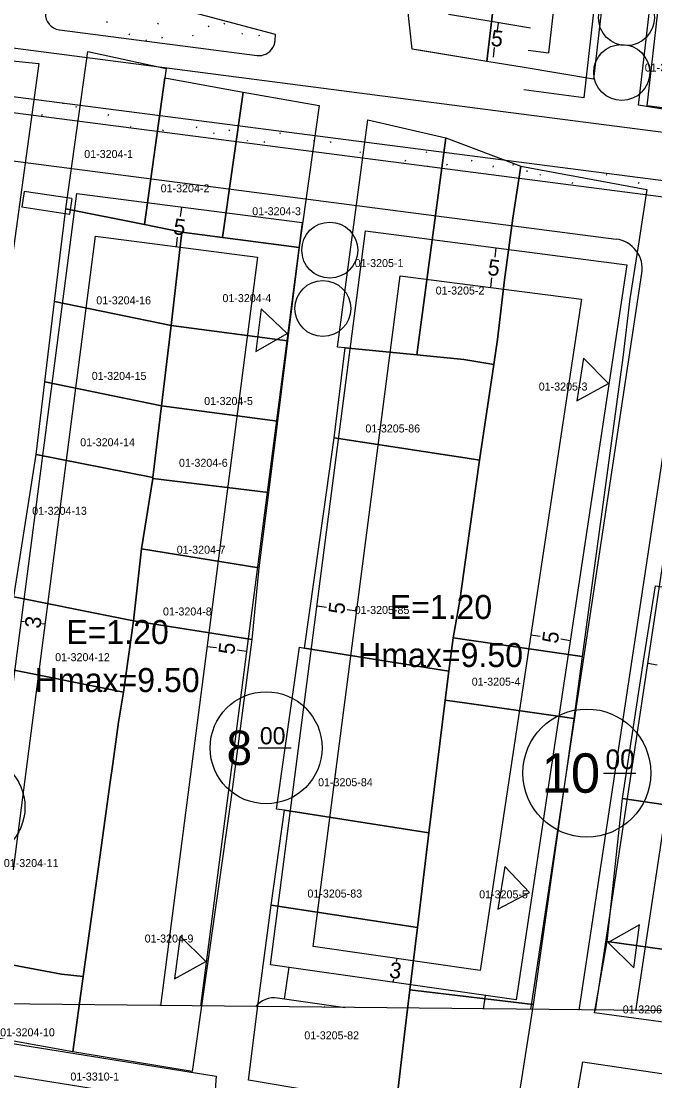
# Model space of a CAD drawing. Extents: x 419396 to 421519, y 4453567 to 4456767.
# Drawn here: x 420470.7 to 420549.9, y 4454304 to 4454436.5 of the extents above; entities that cross this region are included whole.
import ezdxf

# ---------------------------------------------------------------- set-up
doc = ezdxf.new("R2010")
doc.units = 0
for name, color, linetype in [('0_KADASTRO', 7, 'Continuous'), ('Level 16', 7, 'Continuous'), ('Level 20', 7, 'Continuous'), ('Level 28', 7, 'Continuous'), ('Level 29', 7, 'Continuous'), ('Level 30', 7, 'Continuous'), ('Level 41', 7, 'Continuous'), ('Level 53', 7, 'Continuous'), ('Level 55', 7, 'Continuous'), ('Level 58', 7, 'Continuous'), ('Level 62', 7, 'Continuous'), ('Y_Lejant', 7, 'Continuous')]:
    doc.layers.add(name, color=color, linetype=linetype)

msp = doc.modelspace()

# ---------------------------------------------------------------- linework, layer by layer
at = {"layer": '0_KADASTRO'}
for points in [[(420517.81, 4454449.01), (420521.76, 4454448.38), (420530.73, 4454446.96), (420528.91, 4454431.42), (420520.67, 4454432.78), (420519.55, 4454432.97)], [(420528.91, 4454431.42), (420530.73, 4454446.96), (420531.74, 4454446.8), (420544.03, 4454444.85), (420542.26, 4454429.23), (420533.58, 4454430.66)], [(420547.89, 4454425.95), (420548.01, 4454426.99), (420549.96, 4454443.91), (420562.54, 4454441.84), (420560.5, 4454423.87)], [(420476.26, 4454413.01), (420479.02, 4454432.68), (420488.79, 4454430.55), (420488.63, 4454429.4), (420486.07, 4454411.03)], [(420463.19, 4454405.98), (420463.73, 4454432.07), (420472.89, 4454431.17), (420469.31, 4454405.36)], [(420486.07, 4454411.03), (420488.63, 4454429.4), (420498.45, 4454427.58), (420495.85, 4454409.42), (420490.77, 4454410.08)], [(420495.85, 4454409.42), (420498.45, 4454427.58), (420507.93, 4454425.92), (420505.44, 4454408.19)], [(420510.21, 4454395.72), (420514.01, 4454424.15), (420523.76, 4454421.89), (420520.14, 4454394.75), (420511.17, 4454395.62)], [(420520.14, 4454394.75), (420523.76, 4454421.89), (420533.17, 4454418.32), (420532.14, 4454411.84), (420531.11, 4454404.12), (420530.25, 4454396.67), (420529.78, 4454393.54), (420526.05, 4454394.18)], [(420524.69, 4454359.39), (420525.54, 4454364.05), (420526.73, 4454372.71), (420527.97, 4454381.62), (420529.78, 4454393.54), (420530.25, 4454396.67), (420531.11, 4454404.12), (420532.14, 4454411.84), (420533.17, 4454418.32), (420548.92, 4454415.41), (420547.91, 4454408.9), (420546.8, 4454401.78), (420545.92, 4454394.45), (420540.84, 4454357.06)], [(420474.82, 4454401.44), (420476.26, 4454413.01), (420486.07, 4454411.03), (420490.77, 4454410.08), (420489.42, 4454398.42)], [(420489.42, 4454398.42), (420490.77, 4454410.08), (420495.85, 4454409.42), (420505.44, 4454408.19), (420503.99, 4454396.5)], [(420473.61, 4454391.38), (420474.82, 4454401.44), (420489.42, 4454398.42), (420488.22, 4454388.39)], [(420488.22, 4454388.39), (420489.42, 4454398.42), (420503.99, 4454396.5), (420502.74, 4454386.48)], [(420509.81, 4454384.38), (420511.17, 4454395.62), (420520.14, 4454394.75), (420526.05, 4454394.18), (420529.78, 4454393.54), (420527.97, 4454381.62), (420526.19, 4454381.89), (420524.51, 4454382.14)], [(420472.53, 4454382.3), (420473.61, 4454391.38), (420488.22, 4454388.39), (420487.15, 4454379.44), (420483.97, 4454380.07)], [(420487.13, 4454379.3), (420487.15, 4454379.44), (420488.22, 4454388.39), (420502.74, 4454386.48), (420501.6, 4454377.55)], [(420506.1, 4454358.12), (420508.55, 4454375.47), (420509.81, 4454384.38), (420524.51, 4454382.14), (420526.19, 4454381.89), (420527.97, 4454381.62), (420526.73, 4454372.71), (420525.54, 4454364.05), (420524.69, 4454359.39), (420524.16, 4454355.23), (420523.36, 4454355.36)], [(420469.75, 4454364.53), (420472.53, 4454382.3), (420483.97, 4454380.07), (420487.15, 4454379.44), (420487.13, 4454379.3), (420485.73, 4454370.5), (420484.71, 4454361.53), (420482.21, 4454362.03)], [(420485.73, 4454370.5), (420487.13, 4454379.3), (420501.6, 4454377.55), (420500.39, 4454368.16)], [(420484.71, 4454361.53), (420485.73, 4454370.5), (420500.39, 4454368.16), (420499.53, 4454359.17)], [(420545.88, 4454339.32), (420548.57, 4454357.03), (420549.99, 4454365.88), (420564.3, 4454363.71), (420579.28, 4454361.42), (420575.3, 4454334.97)], [(420468.56, 4454355.59), (420469.75, 4454364.53), (420482.21, 4454362.03), (420484.71, 4454361.53), (420483.46, 4454352.62), (420481.02, 4454353.11), (420469.35, 4454355.44)], [(420477.11, 4454307.65), (420478.42, 4454317.06), (420480.49, 4454331.99), (420481.79, 4454341.35), (420482.11, 4454343.64), (420482.84, 4454348.86), (420483.46, 4454352.62), (420484.71, 4454361.53), (420499.53, 4454359.17), (420496.85, 4454338.86), (420492.03, 4454305.19)], [(420523.71, 4454351.6), (420524.16, 4454355.23), (420524.69, 4454359.39), (420540.84, 4454357.06), (420539.78, 4454349.33), (420538.68, 4454349.49), (420526.41, 4454351.22)], [(420502.61, 4454338), (420505.49, 4454358.21), (420506.1, 4454358.12), (420523.36, 4454355.36), (420524.16, 4454355.23), (420523.71, 4454351.6), (420521.65, 4454335.01), (420503.6, 4454337.85)], [(420464.15, 4454319.52), (420465.35, 4454328.46), (420468.56, 4454355.59), (420469.35, 4454355.44), (420481.02, 4454353.11), (420483.46, 4454352.62), (420482.84, 4454348.86), (420482.11, 4454343.64), (420481.79, 4454341.35), (420480.49, 4454331.99), (420478.42, 4454317.06), (420475.72, 4454317.38), (420464.78, 4454319.41)], [(420519.29, 4454315.41), (420520.23, 4454323.21), (420521.65, 4454335.01), (420523.71, 4454351.6), (420526.41, 4454351.22), (420538.68, 4454349.49), (420539.78, 4454349.33), (420534.7, 4454313.56)], [(420543.95, 4454321.44), (420545.88, 4454339.32), (420575.3, 4454334.97), (420573.98, 4454326.07), (420560.65, 4454327.96), (420559.3, 4454319.29), (420558.31, 4454319.44)], [(420501.92, 4454325.99), (420503.6, 4454337.85), (420521.65, 4454335.01), (420520.23, 4454323.21)], [(420499.08, 4454304.11), (420500.26, 4454313.42), (420501.92, 4454325.99), (420520.23, 4454323.21), (420519.29, 4454315.41), (420518.71, 4454310.59), (420517.55, 4454300.99)], [(420542.37, 4454312.53), (420543.95, 4454321.44), (420558.31, 4454319.44), (420556.51, 4454310.61)], [(420463.48, 4454310.11), (420464.78, 4454319.41), (420475.72, 4454317.38), (420478.42, 4454317.06), (420477.11, 4454307.65)], [(420517.03, 4454297.83), (420517.4, 4454300.09), (420517.4, 4454300.1), (420517.55, 4454300.99), (420518.71, 4454310.59), (420519.29, 4454315.41), (420534.7, 4454313.56), (420531.93, 4454295.77), (420519.85, 4454297.44)], [(420465.63, 4454305.27), (420466.42, 4454309.19), (420495.07, 4454304.61), (420494.76, 4454300.61)], [(420539.38, 4454297.51), (420540.9, 4454306.39), (420569.61, 4454302.15), (420568.22, 4454293.26), (420562.81, 4454294.18), (420555.36, 4454295.46), (420554.37, 4454295.62), (420553.37, 4454295.8), (420541.97, 4454297.2)]]:
    msp.add_lwpolyline(points, close=True, dxfattribs=at)
at = {"layer": 'Level 16'}
for p, q in [((420500.69, 4454400.53), (420500.03, 4454395.17)), ((420503.93, 4454397.41), (420500.69, 4454400.53)), ((420500.03, 4454395.17), (420503.93, 4454397.41)), ((420540.98, 4454394.36), (420540.18, 4454389.02)), ((420544.14, 4454391.16), (420540.98, 4454394.36)), ((420540.18, 4454389.02), (420544.14, 4454391.16)), ((420531.14, 4454330.83), (420530.28, 4454325.5)), ((420534.26, 4454327.59), (420531.14, 4454330.83)), ((420530.28, 4454325.5), (420534.26, 4454327.59)), ((420548.02, 4454323.52), (420544.09, 4454321.34)), ((420547.29, 4454318.17), (420548.02, 4454323.52)), ((420490.56, 4454322.12), (420489.82, 4454316.77)), ((420493.76, 4454318.95), (420490.56, 4454322.12)), ((420544.09, 4454321.34), (420547.29, 4454318.17)), ((420489.82, 4454316.77), (420493.76, 4454318.95))]:
    msp.add_line(p, q, dxfattribs=at)
at = {"layer": 'Level 20'}
for p, q in [((420544.46, 4454501.85), (420536.64, 4454432.5)), ((420530.32, 4454436.22), (420530.17, 4454435.03)), ((420529.73, 4454431.98), (420529.88, 4454433.17)), ((420534.06, 4454432.84), (420536.64, 4454432.5)), ((420490.72, 4454413.23), (420490.57, 4454412.04)), ((420467.77, 4454315.93), (420479.94, 4454409.59)), ((420479.94, 4454409.59), (420500.22, 4454406.96)), ((420490.08, 4454408.28), (420490.23, 4454409.47)), ((420530.04, 4454408.15), (420529.89, 4454406.96)), ((420500.22, 4454406.96), (420488.07, 4454313.42)), ((420507.18, 4454320.82), (420518.07, 4454404.65)), ((420518.07, 4454404.65), (420540.73, 4454401.72)), ((420529.4, 4454403.19), (420529.55, 4454404.38)), ((420540.73, 4454401.72), (420528.08, 4454317.83)), ((420547.54, 4454312.79), (420560.57, 4454399.16)), ((420507.67, 4454363.38), (420508.86, 4454363.23)), ((420512.63, 4454362.74), (420511.44, 4454362.89)), ((420470.66, 4454361.47), (420471.06, 4454361.42)), ((420473.64, 4454361.09), (420473.24, 4454361.14)), ((420534.4, 4454359.78), (420535.59, 4454359.6)), ((420539.35, 4454359.03), (420538.16, 4454359.21)), ((420493.9, 4454358.33), (420495.09, 4454358.17)), ((420498.86, 4454357.69), (420497.67, 4454357.84)), ((420549.04, 4454356.22), (420550.22, 4454356.04)), ((420528.08, 4454317.83), (420507.18, 4454320.82)), ((420517.63, 4454319.33), (420517.57, 4454318.93)), ((420517.2, 4454316.36), (420517.26, 4454316.75))]:
    msp.add_line(p, q, dxfattribs=at)
msp.add_lwpolyline([(420534.35, 4454435.6), (420529.72, 4454436.36), (420524.11, 4454437.28)], dxfattribs=at)
at = {"layer": 'Level 28'}
for p, q in [((420475.44, 4454435.38), (420500.17, 4454432.18)), ((420502.42, 4454434.06), (420502.46, 4454434.79)), ((420532.58, 4454314.16), (420501.84, 4454318.55)), ((420503.6, 4454314.26), (420504.17, 4454318.22)), ((420528.48, 4454312.99), (420528.73, 4454314.71)), ((420511.19, 4454313.17), (420502.74, 4454314.38))]:
    msp.add_line(p, q, dxfattribs=at)
msp.add_lwpolyline([(420502.46, 4454434.79), (420493.86, 4454437.09), (420484.83, 4454439.5), (420474.97, 4454442.13)], dxfattribs=at)
for centre, radius, start, end in [((420475.69, 4454437.36), 2, 177.0363, 262.6282), ((420500.42, 4454434.16), 2, 285.8152, 357.0363), ((420500.42, 4454434.16), 2, 262.6282, 285.8152), ((420502.31, 4454311.41), 3, 81.8699, 141.1793)]:
    msp.add_arc(centre, radius, start, end, dxfattribs=at)
at = {"layer": 'Level 29'}
for p, q in [((420548.97, 4454425.86), (420557.93, 4454505.32)), ((420549.6, 4454502.77), (420541.04, 4454426.89)), ((420541.04, 4454426.89), (420533.53, 4454427.86)), ((420569.38, 4454423.22), (420548.97, 4454425.86)), ((420464.81, 4454316.41), (420477.61, 4454414.93)), ((420477.61, 4454414.93), (420505.82, 4454411.28)), ((420505.82, 4454411.28), (420493.1, 4454313.37)), ((420501.84, 4454318.55), (420513.75, 4454410.25)), ((420513.75, 4454410.25), (420546.44, 4454406.03)), ((420546.44, 4454406.03), (420532.58, 4454314.16)), ((420542.49, 4454312.84), (420556.36, 4454404.74))]:
    msp.add_line(p, q, dxfattribs=at)
for points in [[(420519.55, 4454432.97), (420517.81, 4454449.01), (420516.85, 4454457.96), (420515.87, 4454466.9), (420514.85, 4454476.35), (420513.83, 4454485.79), (420512.08, 4454501.85)], [(420533.82, 4454430.62), (420533.58, 4454430.66), (420528.91, 4454431.42), (420519.55, 4454432.97)]]:
    msp.add_lwpolyline(points, dxfattribs=at)
at = {"layer": 'Level 41'}
for p, q in [((420481.39, 4454436.28), (420481.47, 4454436.44)), ((420487.76, 4454436.07), (420487.83, 4454436.23)), ((420494.07, 4454435.86), (420494.14, 4454435.75)), ((420496.05, 4454436.07), (420496.12, 4454436.23)), ((420484.17, 4454434.75), (420484.24, 4454434.91)), ((420486.26, 4454434.13), (420486.33, 4454434.03)), ((420488.25, 4454434.34), (420488.32, 4454434.5)), ((420492.08, 4454434.74), (420492.15, 4454434.63)), ((420498.27, 4454434.93), (420498.35, 4454434.82)), ((420500.37, 4454434.74), (420500.44, 4454434.63)), ((420471.64, 4454426.74), (420471.66, 4454426.79)), ((420475.86, 4454426.25), (420475.88, 4454426.13)), ((420473.25, 4454424.68), (420473.32, 4454424.84)), ((420477.49, 4454425.82), (420477.56, 4454425.72)), ((420481.54, 4454424.68), (420481.62, 4454424.84)), ((420484.32, 4454423.15), (420484.39, 4454423.31)), ((420492.61, 4454423.15), (420492.68, 4454423.31)), ((420488.4, 4454422.74), (420488.47, 4454422.9)), ((420494.7, 4454422.53), (420494.78, 4454422.43)), ((420496.69, 4454422.74), (420496.76, 4454422.9)), ((420503, 4454422.53), (420503.07, 4454422.43)), ((420498.91, 4454421.6), (420498.98, 4454421.5)), ((420501.01, 4454421.41), (420501.08, 4454421.31)), ((420507.21, 4454421.6), (420507.28, 4454421.5)), ((420509.3, 4454421.41), (420509.38, 4454421.31)), ((420513.04, 4454420.15), (420513.11, 4454420.04)), ((420521.34, 4454420.15), (420521.41, 4454420.04)), ((420518.69, 4454418.96), (420518.77, 4454419.12)), ((420521.44, 4454418.34), (420521.47, 4454418.39)), ((420523.86, 4454418.57), (420523.93, 4454418.47)), ((420526.99, 4454418.96), (420527.06, 4454419.12)), ((420529.69, 4454418.23), (420529.76, 4454418.39)), ((420532.15, 4454418.57), (420532.22, 4454418.47)), ((420533.91, 4454417.78), (420533.93, 4454417.62)), ((420535.54, 4454417.31), (420535.61, 4454417.21)), ((420542.22, 4454417.67), (420542.22, 4454417.62)), ((420543.83, 4454417.31), (420543.9, 4454417.21)), ((420539.6, 4454416.17), (420539.67, 4454416.33)), ((420547.89, 4454416.17), (420547.96, 4454416.33)), ((420500.29, 4454313.34), (420500.32, 4454313.29)), ((420508.58, 4454313.34), (420508.65, 4454313.23))]:
    msp.add_line(p, q, dxfattribs=at)
at = {"layer": 'Level 53'}
for p, q in [((420471.05, 4454415.18), (420470.75, 4454413.2)), ((420476.98, 4454414.3), (420471.05, 4454415.18)), ((420476.98, 4454414.3), (420476.69, 4454412.32)), ((420476.69, 4454412.32), (420470.75, 4454413.2))]:
    msp.add_line(p, q, dxfattribs=at)
at = {"layer": 'Level 55'}
for centre in [(420546.37, 4454436.9), (420545.78, 4454430.05), (420509.26, 4454407.85), (420508.4, 4454400.55)]:
    msp.add_circle(centre, 3.5, dxfattribs=at)
at = {"layer": 'Level 58'}
for p, q in [((420500.3, 4454345.66), (420504.44, 4454345.66)), ((420543.5, 4454342.5), (420547.56, 4454342.5))]:
    msp.add_line(p, q, dxfattribs=at)
for centre, radius in [((420501.3, 4454345.66), 7), ((420541.41, 4454342.5), 8), ((420464.64, 4454338.24), 6.5)]:
    msp.add_circle(centre, radius, dxfattribs=at)
at = {"layer": 'Level 62'}
for p, q in [((420463.14, 4454433.95), (420533.21, 4454424.88)), ((420450.41, 4454429.54), (420609.29, 4454408.99)), ((420466.6, 4454425.43), (420611.27, 4454406.71)), ((420533.21, 4454424.88), (420533.21, 4454424.88)), ((420533.21, 4454424.88), (420611.78, 4454414.72)), ((420466.74, 4454419.36), (420545.09, 4454409.23)), ((420534.41, 4454312.93), (420548.3, 4454404.96)), ((420540.47, 4454312.87), (420554.24, 4454404.1))]:
    msp.add_line(p, q, dxfattribs=at)
msp.add_arc((420544.61, 4454405.52), 3.74, 351.4204, 82.6282, dxfattribs=at)
at = {"layer": 'Y_Lejant'}
msp.add_lwpolyline([(420209.76, 4455704.6), (421518.56, 4455690.86), (421518.56, 4454302.65), (420195.09, 4454316.54)], close=True, dxfattribs=at)

# ---------------------------------------------------------------- texts
at = {"layer": '0_KADASTRO'}
for s, p in [('01-3199-178', (420548.66, 4454430.16)), ('01-3204-1', (420478.55, 4454419.36)), ('01-3204-2', (420488.11, 4454415.07)), ('01-3204-3', (420499.56, 4454412.21)), ('01-3205-1', (420512.38, 4454405.73)), ('01-3204-16', (420480.06, 4454401.07)), ('01-3204-4', (420495.84, 4454401.35)), ('01-3205-2', (420522.51, 4454402.3)), ('01-3204-15', (420479.49, 4454391.63)), ('01-3205-3', (420535.4, 4454390.3)), ('01-3204-5', (420493.55, 4454388.49)), ('01-3205-86', (420513.72, 4454385.06)), ('01-3204-14', (420478.05, 4454383.34)), ('01-3204-6', (420490.4, 4454380.77)), ('01-3204-13', (420472.04, 4454374.77)), ('01-3204-7', (420490.12, 4454369.91)), ('01-3204-8', (420488.4, 4454362.19)), ('01-3205-85', (420512.38, 4454362.38)), ('01-3204-12', (420474.91, 4454356.48)), ('01-3205-4', (420527.02, 4454353.42)), ('01-3205-84', (420507.8, 4454340.85)), ('01-3204-11', (420468.49, 4454330.75)), ('01-3205-83', (420506.47, 4454326.94)), ('01-3205-5', (420527.95, 4454326.84)), ('01-3204-9', (420486.11, 4454321.32)), ('01-3206-10', (420545.91, 4454312.46)), ('01-3204-10', (420468.03, 4454309.6)), ('01-3205-82', (420506.08, 4454309.22)), ('01-3310-1', (420476.82, 4454304.07))]:
    msp.add_text(s, height=1, dxfattribs=at).set_placement(p)
at = {"layer": 'Level 20'}
for s, rotation, p in [('5', 352.6282, (420529.33, 4454433.41)), ('5', 352.6282, (420489.61, 4454409.85)), ('5', 352.6282, (420528.93, 4454404.76)), ('5', 82.6002, (420511.05, 4454362.27)), ('3', 82.6002, (420473.06, 4454360.49)), ('5', 81.4204, (420537.77, 4454358.6)), ('5', 82.6002, (420497.29, 4454357.22)), ('3', 351.8699, (420516.61, 4454316.95))]:
    msp.add_text(s, height=2, rotation=rotation, dxfattribs=at).set_placement(p)
at = {"layer": 'Level 30'}
for s, p in [('E=1.20', (420516.75, 4454361.75)), ('E=1.20', (420476.3, 4454358.62)), ('Hmax=9.50', (420512.81, 4454355.75)), ('Hmax=9.50', (420472.36, 4454352.62))]:
    msp.add_text(s, height=3, dxfattribs=at).set_placement(p)
at = {"layer": 'Level 58'}
for s, height, p in [('8', 4.3, (420496.35, 4454343.5)), ('00', 2.152, (420500.52, 4454346.09)), ('00', 2.46, (420543.75, 4454342.99)), ('10', 4.919, (420535.76, 4454340.04))]:
    msp.add_text(s, height=height, dxfattribs=at).set_placement(p)

doc.saveas('drawing.dxf')
